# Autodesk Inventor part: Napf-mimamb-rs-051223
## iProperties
Created: 2005-12
Part Number: Napf-mimamb-rs-051223
Document SubType Name: Modeling
Designer: rsc
Author: rsc
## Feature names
1. Drehung1 [Revolution]
2. Grenzpositionen [Rectangular Pattern]
3. Infinitesimalversatz [Rectangular Pattern]
4. Spiegeln1 [Mirror]
5. Trennen3
6. Trennen4
